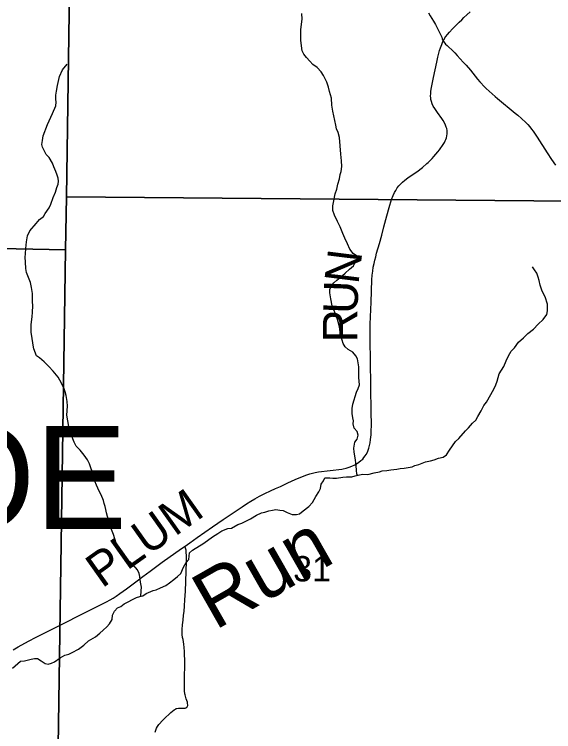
# Model space of a CAD drawing. Extents: x 0 to 34, y 0 to 22.
# Drawn here: x 3.604 to 4.496, y 15.062 to 16.248 of the extents above; entities that cross this region are included whole.
import ezdxf

# ---------------------------------------------------------------- set-up
doc = ezdxf.new("R2010")
doc.units = 0
for name, color, linetype in [('GM_X_Corporation', 7, 'Continuous'), ('GM_X_County_Road_Text', 7, 'Continuous'), ('GM_X_Interstate_Route', 7, 'Continuous'), ('GM_X_Major_Lake', 7, 'Continuous'), ('GM_X_Minor_Lake', 7, 'Continuous'), ('GM_X_Section_Text', 7, 'Continuous'), ('GM_X_Township_Road_Text', 7, 'Continuous'), ('GM_X_US_Shield', 7, 'Continuous')]:
    doc.layers.add(name, color=color, linetype=linetype)

msp = doc.modelspace()

# ---------------------------------------------------------------- linework, layer by layer
at = {"layer": 'GM_X_Corporation'}
for points in [[(3.6016, 15.1975), (3.6101, 15.2025), (3.6273, 15.212), (3.6398, 15.2185), (3.6817, 15.2397), (3.7175, 15.2576), (3.7561, 15.277), (3.7623, 15.2804), (3.7671, 15.2831), (3.7722, 15.2863), (3.7782, 15.2905), (3.7894, 15.2984), (3.8044, 15.31), (3.8163, 15.3189), (3.8284, 15.3276), (3.8484, 15.3423), (3.8799, 15.3649), (3.886, 15.369), (3.8937, 15.3746), (3.9062, 15.3834), (3.9314, 15.4007), (3.9489, 15.4129), (3.9705, 15.4273), (3.9802, 15.4338), (3.9875, 15.4387), (3.9946, 15.4433), (4.0014, 15.4473), (4.009, 15.4514), (4.018, 15.4561), (4.0272, 15.4602), (4.0355, 15.464), (4.0437, 15.4678), (4.0558, 15.4734), (4.0684, 15.479), (4.0805, 15.4843), (4.0875, 15.487), (4.0922, 15.4886), (4.0968, 15.4898), (4.1012, 15.4908), (4.1069, 15.4917), (4.1258, 15.494), (4.1452, 15.4964), (4.1474, 15.4968), (4.1524, 15.498), (4.1572, 15.4995), (4.1621, 15.5014), (4.1667, 15.5035), (4.1696, 15.5052), (4.1733, 15.5077), (4.1768, 15.5103), (4.1798, 15.513), (4.1818, 15.5153), (4.184, 15.5182), (4.1855, 15.5206), (4.1876, 15.5246), (4.1889, 15.5276), (4.19, 15.5309), (4.1912, 15.5351), (4.1921, 15.5395), (4.193, 15.5455), (4.1938, 15.5528), (4.1941, 15.5572), (4.1944, 15.5705), (4.1941, 15.5901), (4.1925, 15.6761), (4.192, 15.7091), (4.1924, 15.7362), (4.1937, 15.7724), (4.195, 15.8092), (4.1957, 15.8168), (4.1964, 15.8234), (4.1974, 15.8302), (4.1986, 15.8361), (4.1999, 15.842), (4.2013, 15.8474), (4.2029, 15.8533), (4.2075, 15.8693), (4.2113, 15.8829), (4.2148, 15.8966), (4.2195, 15.9148), (4.2234, 15.9289), (4.2275, 15.9422), (4.23, 15.9487), (4.2323, 15.9534), (4.2344, 15.957), (4.2371, 15.9611), (4.2397, 15.9647), (4.2424, 15.9674), (4.2458, 15.9708), (4.2495, 15.974), (4.2544, 15.9777), (4.2598, 15.9817), (4.2659, 15.9856), (4.2715, 15.9895), (4.2767, 15.9933), (4.279, 15.9952), (4.2862, 16.0014), (4.2879, 16.003), (4.2948, 16.01), (4.2975, 16.0129), (4.3044, 16.0211), (4.307, 16.0244), (4.3131, 16.0331), (4.315, 16.0361), (4.3165, 16.0389), (4.3174, 16.0411), (4.3183, 16.0441), (4.3191, 16.0474), (4.3195, 16.0505), (4.3193, 16.0561), (4.3188, 16.0592), (4.3181, 16.0616), (4.317, 16.0648), (4.3152, 16.0687), (4.3131, 16.0725), (4.3107, 16.0762), (4.3037, 16.0861), (4.2989, 16.0926), (4.2966, 16.0963), (4.2949, 16.1), (4.2936, 16.1039), (4.2928, 16.1072), (4.2924, 16.1098), (4.2922, 16.1132), (4.2924, 16.1169), (4.2928, 16.1214), (4.2936, 16.1272), (4.2969, 16.1438), (4.2996, 16.1566), (4.3023, 16.1688), (4.3041, 16.1771), (4.3058, 16.1839), (4.307, 16.1881), (4.3085, 16.1927), (4.3107, 16.1984), (4.3125, 16.203), (4.313, 16.2042), (4.3144, 16.2067), (4.3159, 16.2092), (4.3176, 16.2116), (4.3202, 16.215), (4.3236, 16.2189), (4.3285, 16.2243), (4.3318, 16.2276), (4.3349, 16.2308), (4.3393, 16.235), (4.3436, 16.2391), (4.3474, 16.2428), (4.3523, 16.2473), (4.3577, 16.2522)], [(4.2886, 16.2504), (4.2916, 16.2455), (4.2969, 16.2369), (4.3002, 16.2311), (4.3057, 16.2205), (4.3085, 16.2149), (4.3106, 16.2104), (4.3115, 16.2076), (4.3126, 16.2049), (4.313, 16.2042), (4.3136, 16.2031), (4.3155, 16.2005), (4.3168, 16.1991), (4.3193, 16.1965), (4.3222, 16.1938), (4.3274, 16.1893), (4.3321, 16.1847), (4.3363, 16.18), (4.346, 16.1693), (4.3508, 16.1639), (4.358, 16.1559), (4.3699, 16.1412), (4.3737, 16.1367), (4.3818, 16.1279), (4.3842, 16.1255), (4.3992, 16.1121), (4.4027, 16.1091), (4.4323, 16.0848), (4.4366, 16.0812), (4.4425, 16.0762), (4.4499, 16.0694), (4.453, 16.0662), (4.4565, 16.0621), (4.4592, 16.0584), (4.4616, 16.0552), (4.4683, 16.0449), (4.4852, 16.019), (4.4923, 16.0084), (4.4987, 15.999)]]:
    msp.add_lwpolyline(points, dxfattribs=at)
at = {"layer": 'GM_X_Interstate_Route'}
for points in [[(3.8853, 15.1491), (3.8855, 15.1757), (3.8852, 15.195), (3.8847, 15.2014), (3.8841, 15.2071), (3.8827, 15.2149), (3.882, 15.218), (3.8814, 15.2227), (3.8813, 15.2244), (3.8815, 15.2314), (3.882, 15.2391), (3.8828, 15.2464), (3.8837, 15.2547), (3.8843, 15.261), (3.885, 15.2702), (3.8858, 15.2804), (3.8865, 15.2944), (3.8877, 15.3268), (3.8884, 15.3443), (3.8885, 15.3512), (3.888, 15.3608), (3.8876, 15.3625), (3.887, 15.3659), (3.886, 15.369)], [(3.8366, 15.0617), (3.8374, 15.065), (3.8387, 15.0681), (3.8403, 15.071), (3.8426, 15.0741), (3.8435, 15.0753), (3.8479, 15.08), (3.8513, 15.0833), (3.8544, 15.0863), (3.8591, 15.0909), (3.8627, 15.0942), (3.8653, 15.0964), (3.868, 15.0985), (3.87, 15.0997), (3.8715, 15.1005), (3.8725, 15.1008), (3.8752, 15.1012), (3.8823, 15.101), (3.8844, 15.1009), (3.8863, 15.1012), (3.8875, 15.1016), (3.8889, 15.1026), (3.8897, 15.1035), (3.8903, 15.1046), (3.8906, 15.1058), (3.8903, 15.1097), (3.8898, 15.1113), (3.8879, 15.1165), (3.8872, 15.1188), (3.886, 15.1232), (3.8857, 15.125), (3.8853, 15.1298), (3.8852, 15.1341), (3.8853, 15.1481), (3.8853, 15.1491)]]:
    msp.add_lwpolyline(points, dxfattribs=at)
at = {"layer": 'GM_X_Minor_Lake'}
for points in [[(3.7042, 16.9849), (4.539, 16.9739), (4.5275, 15.9394), (3.6897, 15.9465), (3.703, 16.8594)], [(3.703, 16.8594), (3.6897, 15.9465), (3.688, 15.8589), (2.684, 15.8792), (2.6993, 16.8906)], [(4.5275, 15.9394), (4.5059, 14.9222), (3.6743, 14.926), (3.688, 15.8589), (3.6897, 15.9465)], [(2.684, 15.8792), (3.688, 15.8589), (3.6743, 14.926), (3.6733, 14.8581), (2.6707, 14.8651)]]:
    msp.add_lwpolyline(points, close=True, dxfattribs=at)
at = {"layer": 'GM_X_Township_Road_Text'}
for points in [[(4.171, 15.4859), (4.1703, 15.4885), (4.1695, 15.4938), (4.169, 15.5022), (4.1681, 15.5113), (4.1669, 15.5182), (4.166, 15.5246), (4.1652, 15.5307), (4.1669, 15.541), (4.1706, 15.546), (4.1724, 15.5525), (4.1708, 15.5586), (4.1658, 15.5638), (4.1642, 15.5714), (4.1645, 15.5764), (4.1637, 15.5813), (4.1624, 15.5881), (4.1623, 15.5965), (4.1637, 15.6038), (4.1695, 15.6236), (4.1724, 15.6298), (4.1746, 15.6359), (4.1742, 15.6416), (4.1737, 15.6477), (4.1734, 15.6656), (4.1726, 15.672), (4.171, 15.6785), (4.1686, 15.6838), (4.1636, 15.6894), (4.1556, 15.6942), (4.1506, 15.6987), (4.1475, 15.704), (4.1459, 15.7093), (4.1431, 15.7184), (4.1414, 15.7313), (4.1394, 15.7396), (4.1378, 15.7453), (4.135, 15.7533), (4.1323, 15.7597), (4.1295, 15.7665), (4.1271, 15.7779), (4.1254, 15.7878), (4.1254, 15.7935), (4.1276, 15.7985), (4.132, 15.8042), (4.1369, 15.8085), (4.1425, 15.8131), (4.1511, 15.8205), (4.1582, 15.8267), (4.1646, 15.8325), (4.1675, 15.8379), (4.1705, 15.8429), (4.1692, 15.8493), (4.1643, 15.8527), (4.1585, 15.8602), (4.1546, 15.8685), (4.1503, 15.878), (4.1471, 15.8859), (4.1428, 15.8969), (4.1381, 15.9059), (4.133, 15.9161), (4.1307, 15.9241), (4.1305, 15.9317), (4.1316, 15.9371), (4.1344, 15.9516), (4.137, 15.9592), (4.1387, 15.9676), (4.1416, 15.976), (4.1427, 15.9833), (4.1445, 15.9886), (4.1451, 15.9966), (4.1446, 16.0058), (4.1437, 16.0168), (4.1427, 16.0309), (4.1414, 16.0445), (4.139, 16.0529), (4.1366, 16.0589), (4.1354, 16.065), (4.1305, 16.0878), (4.1289, 16.098), (4.128, 16.1098), (4.1251, 16.1208), (4.1231, 16.128), (4.1204, 16.136), (4.1149, 16.1473), (4.1114, 16.1533), (4.1045, 16.1601), (4.0976, 16.1653), (4.0926, 16.1706), (4.0868, 16.1769), (4.0826, 16.1822), (4.0799, 16.1879), (4.0778, 16.2004), (4.0773, 16.2053), (4.0776, 16.2156), (4.0775, 16.2225), (4.0788, 16.232), (4.0795, 16.24), (4.0793, 16.2495)], [(3.6726, 16.1029), (3.6721, 16.1078), (3.6724, 16.1147), (3.6731, 16.1211), (3.6748, 16.1303), (3.6784, 16.1456), (3.6831, 16.1563), (3.691, 16.1656)], [(3.8131, 15.286), (3.8135, 15.2951), (3.8138, 15.3012), (3.8125, 15.3095), (3.8112, 15.3186), (3.81, 15.3239), (3.8076, 15.33), (3.8, 15.3382), (3.7919, 15.345), (3.7823, 15.3517), (3.7781, 15.3581), (3.7745, 15.3672), (3.7718, 15.374), (3.7678, 15.3884), (3.7643, 15.3963), (3.7619, 15.4069), (3.7595, 15.4126), (3.7579, 15.4179), (3.7563, 15.424), (3.7551, 15.4297), (3.7539, 15.4346), (3.7523, 15.4395), (3.7511, 15.4444), (3.7475, 15.4539), (3.7437, 15.4596), (3.7397, 15.4698), (3.737, 15.4762), (3.7342, 15.4883), (3.7306, 15.497), (3.7279, 15.505), (3.7244, 15.5114), (3.7189, 15.5193), (3.7124, 15.5276), (3.7059, 15.534), (3.7027, 15.5408), (3.7004, 15.5464), (3.6972, 15.5559), (3.694, 15.5669), (3.692, 15.576), (3.6907, 15.5855), (3.6913, 15.6003), (3.6908, 15.6083), (3.6895, 15.6178), (3.6875, 15.6239), (3.6863, 15.6292), (3.6816, 15.6386), (3.6762, 15.6485), (3.6681, 15.6582), (3.6604, 15.6657), (3.6531, 15.6736), (3.6454, 15.6803), (3.6401, 15.6837), (3.6357, 15.6954), (3.6345, 15.7015), (3.6324, 15.7163), (3.6315, 15.722), (3.6314, 15.7349), (3.6331, 15.7487), (3.6337, 15.7551), (3.6343, 15.7666), (3.6338, 15.773), (3.6336, 15.7867), (3.632, 15.7966), (3.6303, 15.8049), (3.628, 15.8102), (3.626, 15.8159), (3.624, 15.8212), (3.6224, 15.8277), (3.6219, 15.8387), (3.6218, 15.8467), (3.6221, 15.8524), (3.6227, 15.8612), (3.6237, 15.8722), (3.6254, 15.8818), (3.6295, 15.8902), (3.6399, 15.9021), (3.6455, 15.9091), (3.6518, 15.9138), (3.6544, 15.9191), (3.6615, 15.9284), (3.664, 15.9341), (3.6677, 15.9456), (3.6717, 15.954), (3.6739, 15.9617), (3.6761, 15.9674), (3.6764, 15.9724), (3.6759, 15.9773), (3.6747, 15.9822), (3.6723, 15.9883), (3.6692, 15.9959), (3.6665, 16.0023), (3.6614, 16.0113), (3.656, 16.0162), (3.6502, 16.0283), (3.6493, 16.0332), (3.6504, 16.0393), (3.6514, 16.0473), (3.6587, 16.0661), (3.6668, 16.0841), (3.6723, 16.0968), (3.6726, 16.1029)], [(4.2123, 15.4934), (4.2198, 15.4942), (4.2266, 15.4951), (4.2361, 15.4964), (4.2418, 15.4976), (4.2482, 15.4977), (4.2614, 15.5002), (4.2663, 15.5022), (4.2727, 15.5042), (4.2836, 15.5081), (4.2919, 15.5102), (4.298, 15.5118), (4.3051, 15.5142), (4.3127, 15.5162), (4.3183, 15.5197), (4.3235, 15.5278), (4.3335, 15.542), (4.3387, 15.547), (4.3499, 15.5598), (4.3547, 15.5644), (4.3614, 15.5725), (4.3671, 15.5771), (4.3704, 15.5833), (4.3759, 15.5929), (4.3803, 15.6013), (4.3844, 15.6071), (4.3918, 15.6198), (4.3973, 15.6294), (4.3999, 15.6355), (4.4021, 15.6416), (4.4057, 15.6538), (4.4131, 15.6658), (4.4171, 15.6753), (4.4208, 15.6834), (4.4252, 15.6914), (4.4312, 15.6969), (4.4375, 15.7061), (4.4457, 15.7131), (4.4528, 15.7204), (4.4625, 15.7278), (4.47, 15.7359), (4.4786, 15.7436), (4.4845, 15.7521), (4.4856, 15.7582), (4.4854, 15.7688), (4.4814, 15.7813), (4.4768, 15.7904), (4.4736, 15.8003), (4.4716, 15.8082), (4.47, 15.8139), (4.468, 15.82), (4.4641, 15.8256), (4.4607, 15.8305)], [(3.6003, 15.1673), (3.6137, 15.179), (3.6205, 15.1794), (3.6315, 15.1823), (3.6371, 15.1835), (3.6421, 15.1832), (3.6482, 15.1795), (3.6547, 15.175), (3.6596, 15.174), (3.6649, 15.1756), (3.6698, 15.1775), (3.6792, 15.1842), (3.687, 15.1885), (3.6935, 15.1905), (3.6991, 15.1932), (3.7096, 15.1987), (3.7186, 15.2053), (3.7264, 15.2127), (3.7377, 15.2193), (3.7448, 15.2251), (3.7504, 15.2302), (3.7568, 15.2356), (3.7613, 15.2406), (3.7653, 15.2479), (3.766, 15.2548), (3.7693, 15.2613), (3.7745, 15.2671), (3.7798, 15.2694), (3.7854, 15.2737), (3.791, 15.2765), (3.8, 15.2815), (3.8057, 15.2839), (3.811, 15.2855), (3.8162, 15.2867), (3.8219, 15.2906), (3.8331, 15.2957), (3.8384, 15.2966), (3.8456, 15.3001), (3.8542, 15.3041), (3.8602, 15.3083), (3.8673, 15.3138), (3.8737, 15.3188), (3.8789, 15.3238), (3.8837, 15.3342), (3.8877, 15.3419), (3.8922, 15.3469), (3.8929, 15.3522), (3.8936, 15.3579), (3.8984, 15.3622), (3.9168, 15.3739), (3.9314, 15.3844), (3.9404, 15.3899), (3.9468, 15.3942), (3.957, 15.3981), (3.963, 15.3986), (3.9732, 15.4048), (3.9799, 15.4072), (3.989, 15.4115), (3.9942, 15.4143), (4.0044, 15.4202), (4.0122, 15.4241), (4.0179, 15.4253), (4.0247, 15.4273), (4.0304, 15.4285), (4.0364, 15.4294), (4.0429, 15.4284), (4.0482, 15.4281), (4.055, 15.4247), (4.0634, 15.4214), (4.0706, 15.4215), (4.0755, 15.4224), (4.0815, 15.4274), (4.0909, 15.4344), (4.0968, 15.4414), (4.1023, 15.451), (4.1072, 15.4586), (4.1101, 15.4644), (4.1111, 15.4713), (4.1152, 15.4767), (4.117, 15.482), (4.1254, 15.4818), (4.1303, 15.4811), (4.1364, 15.4815), (4.1469, 15.4832), (4.153, 15.4833), (4.1621, 15.4838), (4.1674, 15.4851), (4.1794, 15.4879), (4.1885, 15.4873), (4.1987, 15.4901), (4.2074, 15.4918), (4.2123, 15.4934)]]:
    msp.add_lwpolyline(points, dxfattribs=at)

# ---------------------------------------------------------------- texts
at = {"layer": 'GM_X_County_Road_Text'}
msp.add_text('31', height=0.04186, rotation=0, dxfattribs=at).set_placement((4.0649, 15.3107))
at = {"layer": 'GM_X_Major_Lake'}
for s, height, rotation, p in [('N', 0.0568, 82.9111, (4.1726, 15.8007)), ('U', 0.0568, 87.9815, (4.171, 15.7521)), ('R', 0.0568, 89.9063, (4.1709, 15.7059)), ('PLUM', 0.05682, 35.375, (3.7486, 15.2985))]:
    msp.add_text(s, height=height, rotation=rotation, dxfattribs=at).set_placement(p)
at = {"layer": 'GM_X_Section_Text'}
msp.add_text('MONROE', height=0.17045, rotation=0, dxfattribs=at).set_placement((2.7643, 15.3974))
at = {"layer": 'GM_X_US_Shield'}
msp.add_text('Run', height=0.09469, rotation=29.6968, dxfattribs=at).set_placement((3.9353, 15.229))

doc.saveas('drawing.dxf')
